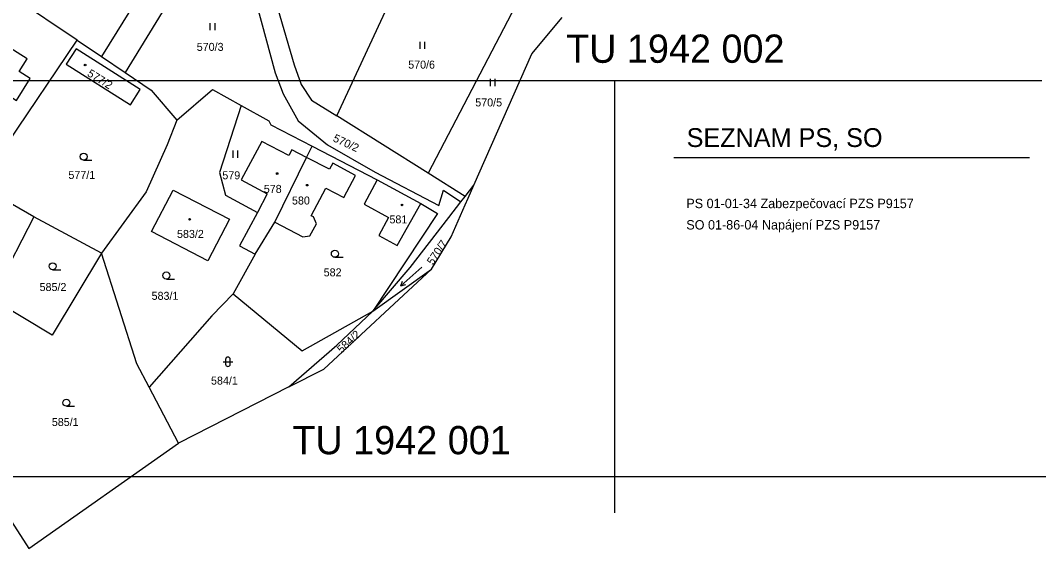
# Model space of a CAD drawing. Extents: x -558500 to -557517, y -1073973 to -1073051.
# Drawn here: x -558126.2 to -557909.9, y -1073799.4 to -1073687.1 of the extents above; entities that cross this region are included whole.
import ezdxf

# ---------------------------------------------------------------- set-up
doc = ezdxf.new("R2010")
doc.units = 0
for name, color, linetype in [('Default', 7, 'Continuous'), ('Hranice parcel', 7, 'Continuous'), ('Parcelní čísla', 7, 'Continuous'), ('Rozpiska_pole_5', 7, 'Continuous'), ('Vrstva 1', 7, 'Continuous'), ('Vrstva 2', 7, 'Continuous'), ('Vrstva 28', 7, 'Continuous'), ('Značky budov', 7, 'Continuous'), ('Značky kultur', 7, 'Continuous')]:
    doc.layers.add(name, color=color, linetype=linetype)

msp = doc.modelspace()

# ---------------------------------------------------------------- linework, layer by layer
at = {"layer": 'Default'}
msp.add_line((-558000, -1073700), (-558000, -1073791.75), dxfattribs=at)
msp.add_lwpolyline([(-557909.21, -1073700), (-558500, -1073700), (-558500, -1073200), (-557800, -1073200), (-557800, -1073567.6)], dxfattribs=at)
at = {"layer": 'Hranice parcel'}
for p, q in [((-558082.19, -1073662.86), (-558103.95, -1073698.19)), ((-558058.98, -1073707.44), (-558042.48, -1073671.96)), ((-558114.13, -1073691.34), (-558128.54, -1073681.64)), ((-558100.81, -1073681.69), (-558108.93, -1073694.83)), ((-558020.18, -1073682.32), (-558039.55, -1073719.63)), ((-558017.53, -1073694.23), (-558011.11, -1073686.54)), ((-558114.13, -1073691.34), (-558108.93, -1073694.83)), ((-558029.85, -1073722.15), (-558017.53, -1073694.23)), ((-558108.93, -1073694.83), (-558103.95, -1073698.19)), ((-558079.26, -1073705.23), (-558083.89, -1073719.49)), ((-558039.55, -1073719.63), (-558058.98, -1073707.44)), ((-558123.29, -1073728.86), (-558153.86, -1073711.3)), ((-558065.38, -1073716.24), (-558064.19, -1073713.89)), ((-558064.19, -1073713.89), (-558050.38, -1073721.04)), ((-558072.16, -1073729.98), (-558065.38, -1073716.24)), ((-558083.89, -1073719.49), (-558082.62, -1073724.25)), ((-558031.72, -1073724.54), (-558039.55, -1073719.63)), ((-558050.38, -1073721.04), (-558041.12, -1073726.03)), ((-558031.72, -1073724.54), (-558029.85, -1073722.15)), ((-558082.62, -1073724.25), (-558075.83, -1073727.93)), ((-558032.62, -1073725.69), (-558031.72, -1073724.54)), ((-558123.29, -1073728.86), (-558132.34, -1073746.32)), ((-558108.92, -1073736.57), (-558123.29, -1073728.86)), ((-558076.28, -1073736.83), (-558072.16, -1073729.98)), ((-558076.28, -1073736.83), (-558080.95, -1073745.27)), ((-558051.32, -1073748.93), (-558043.37, -1073739.61)), ((-558061.7, -1073761.21), (-558038.85, -1073740)), ((-558051.32, -1073748.93), (-558038.85, -1073740)), ((-558080.95, -1073745.27), (-558085.52, -1073749.88)), ((-558085.52, -1073749.88), (-558098.82, -1073765.08)), ((-558058.99, -1073756.15), (-558051.32, -1073748.93)), ((-558069.16, -1073765.01), (-558058.99, -1073756.15)), ((-558069.16, -1073765.01), (-558061.7, -1073761.21)), ((-558092.62, -1073776.97), (-558098.82, -1073765.08)), ((-558069.16, -1073765.01), (-558092.62, -1073776.97)), ((-558124.36, -1073799.37), (-558092.62, -1073776.97))]:
    msp.add_line(p, q, dxfattribs=at)
for points in [[(-558081.56, -1073653.8), (-558077.6, -1073664.88), (-558074.09, -1073675.7), (-558068.03, -1073696.59), (-558066.56, -1073700.76), (-558064.34, -1073704.08), (-558058.98, -1073707.44)], [(-558080.79, -1073666.61), (-558077.98, -1073676.29), (-558072.03, -1073698.27), (-558070.37, -1073702.74), (-558067.15, -1073708.5), (-558060.97, -1073713.55), (-558050.8, -1073719.38), (-558037.27, -1073726.47), (-558036.33, -1073723.21), (-558032.62, -1073725.69)], [(-558157.39, -1073694.14), (-558128.92, -1073713.32), (-558114.13, -1073691.34)], [(-558124.75, -1073695.3), (-558132.74, -1073690.28), (-558139.98, -1073702.13), (-558132.13, -1073707.05), (-558129.35, -1073702.69), (-558127, -1073704.15), (-558124.1, -1073699.49), (-558126.45, -1073698.03), (-558124.75, -1073695.3)], [(-558114.32, -1073693.16), (-558116.42, -1073696.46), (-558102.81, -1073705.11), (-558100.72, -1073701.82), (-558114.32, -1073693.16)], [(-558103.95, -1073698.19), (-558098.36, -1073701.95), (-558092.97, -1073708.36)], [(-558092.97, -1073708.36), (-558085.4, -1073701.82), (-558079.26, -1073705.23)], [(-558079.26, -1073705.23), (-558073.37, -1073708.51), (-558073.01, -1073709.33), (-558064.19, -1073713.89)], [(-558092.97, -1073708.36), (-558095.02, -1073713.61), (-558099.46, -1073723.54), (-558108.92, -1073736.57)], [(-558065.38, -1073716.24), (-558068.48, -1073714.62), (-558069.13, -1073715.86), (-558074.89, -1073712.87), (-558079.25, -1073721.04), (-558073.73, -1073723.99), (-558075.83, -1073727.93)], [(-558072.16, -1073729.98), (-558066.15, -1073733.15), (-558064.66, -1073732.92), (-558063.26, -1073730.33), (-558063.88, -1073728.9), (-558064.4, -1073728.63), (-558061.31, -1073722.78), (-558057.44, -1073724.76), (-558054.98, -1073720.06), (-558059.84, -1073717.49), (-558060.51, -1073718.77), (-558065.38, -1073716.24)], [(-558050.38, -1073721.04), (-558053.17, -1073726.18), (-558047.96, -1073729.01), (-558050.05, -1073732.86), (-558046.14, -1073734.98), (-558041.12, -1073726.03)], [(-558031.69, -1073726.31), (-558031.08, -1073724.94), (-558029.85, -1073722.15)], [(-558081.79, -1073729.39), (-558086.39, -1073738.22), (-558098.32, -1073732.01), (-558093.7, -1073723.21), (-558081.79, -1073729.39)], [(-558041.12, -1073726.03), (-558037.61, -1073728.19), (-558051.32, -1073748.93)], [(-558043.37, -1073739.61), (-558035.2, -1073729), (-558032.62, -1073725.69)], [(-558038.85, -1073740), (-558034.7, -1073733.14), (-558031.69, -1073726.31)], [(-558075.83, -1073727.93), (-558079.61, -1073735.04), (-558076.28, -1073736.83)], [(-558108.92, -1073736.57), (-558119.39, -1073754.05), (-558132.34, -1073746.32)], [(-558098.82, -1073765.08), (-558101.41, -1073760.13), (-558108.92, -1073736.57)], [(-558080.95, -1073745.27), (-558066.32, -1073757.38), (-558051.32, -1073748.93)], [(-558136.25, -1073781.43), (-558134.84, -1073783.14), (-558124.36, -1073799.37)]]:
    msp.add_lwpolyline(points, dxfattribs=at)
at = {"layer": 'Vrstva 1'}
for p, q in [((-557987.36, -1073716.3), (-557911.86, -1073716.3)), ((-557516.53, -1073784.09), (-558357.53, -1073784.09))]:
    msp.add_line(p, q, dxfattribs=at)
at = {"layer": 'Značky budov'}
for centre in [(-558112.42, -1073696.62), (-558071.63, -1073719.68), (-558065.25, -1073722.15), (-558045.1, -1073726.35), (-558090.22, -1073729.39)]:
    msp.add_circle(centre, 0.175, dxfattribs=at)
at = {"layer": 'Značky kultur'}
for p, q in [((-558085.83, -1073689.23), (-558085.83, -1073687.73)), ((-558084.83, -1073689.23), (-558084.83, -1073687.73)), ((-558041.24, -1073693.17), (-558041.24, -1073691.67)), ((-558040.24, -1073693.17), (-558040.24, -1073691.67)), ((-558026.3, -1073701.09), (-558026.3, -1073699.59)), ((-558025.3, -1073701.09), (-558025.3, -1073699.59)), ((-558080.99, -1073716.31), (-558080.99, -1073714.81)), ((-558079.99, -1073716.31), (-558079.99, -1073714.81)), ((-558112.73, -1073716.84), (-558110.98, -1073716.84)), ((-558059.37, -1073737.48), (-558057.62, -1073737.48)), ((-558040.91, -1073739.54), (-558045.37, -1073743.55)), ((-558119.32, -1073740.13), (-558117.57, -1073740.13)), ((-558095.17, -1073742.09), (-558093.42, -1073742.09)), ((-558045.37, -1073743.55), (-558044.98, -1073742.53)), ((-558045.37, -1073743.55), (-558044.31, -1073743.27)), ((-558082.58, -1073759.17), (-558082.58, -1073760.17)), ((-558081.58, -1073760.17), (-558081.58, -1073759.17)), ((-558083.08, -1073759.67), (-558081.08, -1073759.67)), ((-558116.4, -1073769.12), (-558114.65, -1073769.12))]:
    msp.add_line(p, q, dxfattribs=at)
for centre in [(-558112.73, -1073716.09), (-558059.37, -1073736.73), (-558119.32, -1073739.38), (-558095.17, -1073741.34), (-558116.4, -1073768.37)]:
    msp.add_circle(centre, 0.75, dxfattribs=at)
for centre, start, end in [((-558082.08, -1073759.17), 0, 180), ((-558082.08, -1073760.17), 180, 359.9879)]:
    msp.add_arc(centre, 0.5, start, end, dxfattribs=at)

# ---------------------------------------------------------------- texts
at = {"layer": 'Parcelní čísla'}
for s, p in [('570/3', (-558088.71, -1073693.62)), ('570/6', (-558043.8, -1073697.39)), ('570/5', (-558029.55, -1073705.42)), ('577/1', (-558115.97, -1073720.83)), ('579', (-558083.27, -1073720.9)), ('578', (-558074.47, -1073723.79)), ('580', (-558068.48, -1073726.26)), ('581', (-558047.78, -1073730.27)), ('583/2', (-558092.9, -1073733.36)), ('582', (-558061.75, -1073741.52)), ('585/2', (-558122.09, -1073744.64)), ('583/1', (-558098.3, -1073746.51)), ('584/1', (-558085.68, -1073764.52)), ('585/1', (-558119.49, -1073773.32))]:
    msp.add_text(s, height=1.7, dxfattribs=at).set_placement(p)
for s, rotation, p in [('577/2', 328, (-558112.11, -1073698.84)), ('570/2', 335, (-558059.92, -1073712.75)), ('570/7', 56, (-558038.56, -1073739.25)), ('584/2', 43, (-558057.95, -1073757.95))]:
    msp.add_text(s, height=1.7, rotation=rotation, dxfattribs=at).set_placement(p)
at = {"layer": 'Rozpiska_pole_5'}
msp.add_text('SEZNAM PS, SO', height=4, dxfattribs=at).set_placement((-557984.66, -1073714.04))
at = {"layer": 'Vrstva 2'}
for s, p in [('TU 1942 002', (-558010.26, -1073696.15)), ('TU 1942 001', (-558068.41, -1073779.32))]:
    msp.add_text(s, height=6, dxfattribs=at).set_placement(p)
at = {"layer": 'Vrstva 28'}
for s, p in [('PS 01-01-34 Zabezpečovací PZS P9157', (-557984.73, -1073727.03)), ('SO 01-86-04 Napájení PZS P9157', (-557984.73, -1073731.57))]:
    msp.add_text(s, height=2, dxfattribs=at).set_placement(p)

doc.saveas('drawing.dxf')
